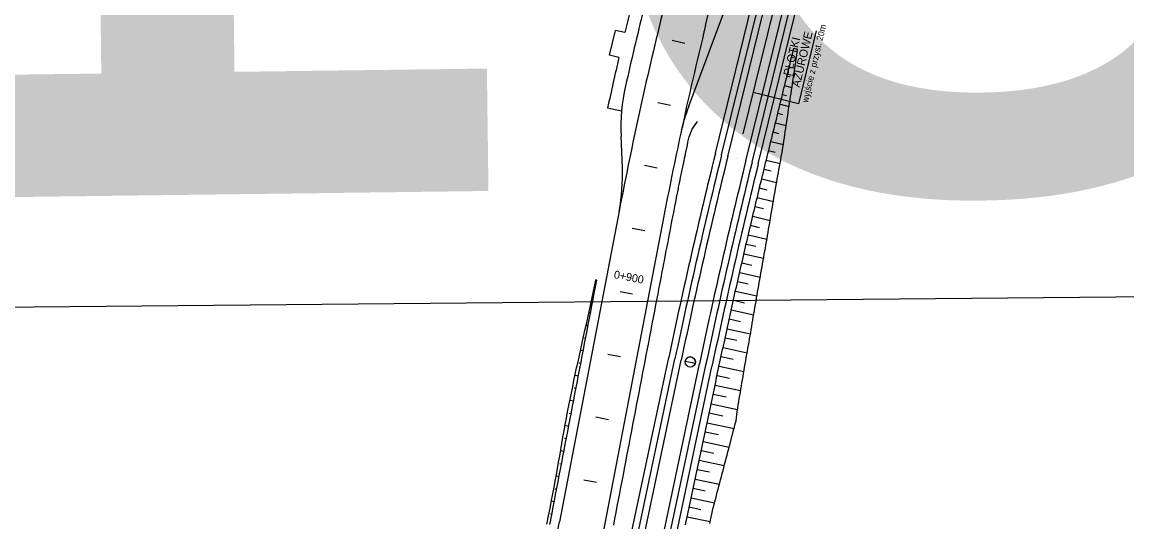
# Model space of a CAD drawing. Extents: x 6503541 to 6503743, y 5888004 to 5888145.
# Drawn here: x 6503704.203 to 6503708.343, y 5888135.392 to 5888137.264 of the extents above; entities that cross this region are included whole.
import ezdxf

# ---------------------------------------------------------------- set-up
doc = ezdxf.new("R2010")
doc.units = 0
doc.layers.add('12', color=7, linetype='Continuous')
doc.layers.add('tabela', color=7, linetype='Continuous')

msp = doc.modelspace()

# ---------------------------------------------------------------- linework, layer by layer
at = {"layer": '12'}
for p, q in [((6503706.9152, 5888136.7445), (6503708.3171, 5888142.443)), ((6503706.9385, 5888136.7388), (6503708.3404, 5888142.4373)), ((6503706.8243, 5888136.7668), (6503708.1987, 5888142.3535)), ((6503706.8476, 5888136.7611), (6503708.222, 5888142.3478)), ((6503706.7644, 5888137.252), (6503706.958, 5888138.0389)), ((6503706.701, 5888136.949), (6503706.8686, 5888137.395)), ((6503706.801, 5888136.7726), (6503706.9378, 5888137.3288)), ((6503707.0189, 5888137.3118), (6503706.9042, 5888136.8457)), ((6503706.9618, 5888136.733), (6503707.0992, 5888137.2916)), ((6503706.4045, 5888137.1396), (6503706.4265, 5888137.2331)), ((6503706.4615, 5888137.2248), (6503706.4265, 5888137.2331)), ((6503707.1781, 5888137.2309), (6503707.113, 5888136.9578)), ((6503707.095, 5888137.1661), (6503707.1093, 5888137.1626)), ((6503706.4395, 5888137.1314), (6503706.4045, 5888137.1396)), ((6503707.0952, 5888137.129), (6503707.0864, 5888137.1311)), ((6503707.0778, 5888137.0962), (6503707.0985, 5888137.0911)), ((6503707.0812, 5888137.0583), (6503707.0692, 5888137.0612)), ((6503707.113, 5888136.9578), (6503706.9421, 5888136.9998)), ((6503707.0606, 5888137.0263), (6503707.0878, 5888137.0196)), ((6503707.0672, 5888136.9876), (6503707.052, 5888136.9913)), ((6503706.3971, 5888136.9429), (6503706.4498, 5888136.9314)), ((6503707.0533, 5888136.9168), (6503707.0348, 5888136.9214)), ((6503707.0434, 5888136.9563), (6503707.0771, 5888136.9481)), ((6503707.0262, 5888136.8864), (6503707.0664, 5888136.8765)), ((6503706.4524, 5888136.72), (6503706.4475, 5888136.8369)), ((6503707.0393, 5888136.8461), (6503707.0176, 5888136.8515)), ((6503707.009, 5888136.8165), (6503707.0557, 5888136.805)), ((6503707.0253, 5888136.7754), (6503707.0004, 5888136.7816)), ((6503707.0101, 5888136.7051), (6503706.9832, 5888136.7116)), ((6503706.9918, 5888136.7466), (6503707.0433, 5888136.7339)), ((6503706.9747, 5888136.6767), (6503707.0306, 5888136.663)), ((6503706.9953, 5888136.6346), (6503706.9662, 5888136.6417)), ((6503706.9577, 5888136.6067), (6503707.0182, 5888136.5921)), ((6503706.4416, 5888136.5624), (6503706.2169, 5888135.3917)), ((6503706.9807, 5888136.5642), (6503706.9493, 5888136.5717)), ((6503706.6066, 5888136.5307), (6503706.3819, 5888135.36)), ((6503706.941, 5888136.5367), (6503707.0061, 5888136.5212)), ((6503706.9245, 5888136.4666), (6503706.9941, 5888136.4503)), ((6503706.9664, 5888136.4937), (6503706.9327, 5888136.5016)), ((6503706.9522, 5888136.4232), (6503706.9163, 5888136.4315)), ((6503706.9082, 5888136.3965), (6503706.9818, 5888136.3795)), ((6503706.9378, 5888136.3527), (6503706.9001, 5888136.3614)), ((6503706.8921, 5888136.3263), (6503706.9691, 5888136.3087)), ((6503706.8762, 5888136.2561), (6503706.9567, 5888136.238)), ((6503706.9235, 5888136.2823), (6503706.8841, 5888136.2912)), ((6503706.9095, 5888136.2117), (6503706.8683, 5888136.2209)), ((6503706.8605, 5888136.1858), (6503706.9445, 5888136.1672)), ((6503706.8956, 5888136.1412), (6503706.8527, 5888136.1506)), ((6503706.845, 5888136.1155), (6503706.9325, 5888136.0964)), ((6503706.8818, 5888136.0707), (6503706.8374, 5888136.0803)), ((6503705.4026, 5888130.2295), (6503706.626, 5888136.008)), ((6503706.8681, 5888136.0001), (6503706.8222, 5888136.0099)), ((6503706.8298, 5888136.0451), (6503706.92, 5888136.0257)), ((6503705.426, 5888130.2245), (6503706.6495, 5888136.003)), ((6503705.4495, 5888130.2195), (6503706.673, 5888135.998)), ((6503705.5176, 5888130.2051), (6503706.7411, 5888135.9836)), ((6503705.5411, 5888130.2001), (6503706.7646, 5888135.9786)), ((6503705.5646, 5888130.1952), (6503706.788, 5888135.9737)), ((6503706.8147, 5888135.9747), (6503706.9078, 5888135.9549)), ((6503706.8545, 5888135.9295), (6503706.8073, 5888135.9395)), ((6503706.7998, 5888135.9042), (6503706.8956, 5888135.884)), ((6503706.841, 5888135.8587), (6503706.7924, 5888135.869)), ((6503706.8285, 5888135.7878), (6503706.7775, 5888135.7986)), ((6503706.7849, 5888135.8338), (6503706.884, 5888135.8128)), ((6503706.77, 5888135.7634), (6503706.8711, 5888135.742)), ((6503706.8122, 5888135.7176), (6503706.7625, 5888135.7281)), ((6503706.7551, 5888135.6929), (6503706.8527, 5888135.6723)), ((6503706.7956, 5888135.6476), (6503706.7476, 5888135.6577)), ((6503706.7402, 5888135.6225), (6503706.8344, 5888135.6025)), ((6503706.7253, 5888135.5521), (6503706.8161, 5888135.5328)), ((6503706.779, 5888135.5775), (6503706.7327, 5888135.5873)), ((6503706.7624, 5888135.5074), (6503706.7178, 5888135.5168)), ((6503706.7103, 5888135.4816), (6503706.7978, 5888135.4631)), ((6503706.746, 5888135.4373), (6503706.7029, 5888135.4464)), ((6503706.6954, 5888135.4112), (6503706.7818, 5888135.3929))]:
    msp.add_line(p, q, dxfattribs=at)
for points in [[(6503706.6863, 5888137.1845), (6503706.6396, 5888137.1957)], [(6503706.689, 5888135.3809), (6503706.6915, 5888135.3926), (6503706.694, 5888135.4044), (6503706.6965, 5888135.4161), (6503706.699, 5888135.4278), (6503706.7014, 5888135.4396), (6503706.7039, 5888135.4513), (6503706.7064, 5888135.4631), (6503706.7089, 5888135.4748), (6503706.7114, 5888135.4865), (6503706.7139, 5888135.4983), (6503706.7164, 5888135.51), (6503706.7188, 5888135.5218), (6503706.7213, 5888135.5335), (6503706.7238, 5888135.5452), (6503706.7263, 5888135.557), (6503706.7288, 5888135.5687), (6503706.7313, 5888135.5804), (6503706.7338, 5888135.5922), (6503706.7362, 5888135.6039), (6503706.7387, 5888135.6157), (6503706.7412, 5888135.6274), (6503706.7437, 5888135.6391), (6503706.7462, 5888135.6509), (6503706.7487, 5888135.6626), (6503706.7512, 5888135.6744), (6503706.7536, 5888135.6861), (6503706.7561, 5888135.6978), (6503706.7586, 5888135.7096), (6503706.7611, 5888135.7213), (6503706.7636, 5888135.7331), (6503706.7661, 5888135.7448), (6503706.7686, 5888135.7565), (6503706.771, 5888135.7683), (6503706.7735, 5888135.78), (6503706.776, 5888135.7918), (6503706.7785, 5888135.8035), (6503706.781, 5888135.8152), (6503706.7835, 5888135.827), (6503706.786, 5888135.8387), (6503706.7884, 5888135.8505), (6503706.7909, 5888135.8622), (6503706.7934, 5888135.8739), (6503706.7959, 5888135.8857), (6503706.7984, 5888135.8974), (6503706.8009, 5888135.9092), (6503706.8034, 5888135.9209), (6503706.8058, 5888135.9326), (6503706.8083, 5888135.9444), (6503706.8108, 5888135.9561), (6503706.8133, 5888135.9679), (6503706.8158, 5888135.9795), (6503706.8183, 5888135.9912), (6503706.8207, 5888136.0029), (6503706.8232, 5888136.0146), (6503706.8257, 5888136.0263), (6503706.8282, 5888136.038), (6503706.8308, 5888136.0496), (6503706.8333, 5888136.0613), (6503706.8358, 5888136.073), (6503706.8383, 5888136.0847), (6503706.8409, 5888136.0963), (6503706.8434, 5888136.108), (6503706.846, 5888136.1197), (6503706.8485, 5888136.1314), (6503706.8511, 5888136.143), (6503706.8536, 5888136.1547), (6503706.8562, 5888136.1664), (6503706.8588, 5888136.178), (6503706.8614, 5888136.1897), (6503706.8639, 5888136.2013), (6503706.8665, 5888136.213), (6503706.8691, 5888136.2247), (6503706.8717, 5888136.2363), (6503706.8744, 5888136.248), (6503706.877, 5888136.2596), (6503706.8796, 5888136.2713), (6503706.8822, 5888136.2829), (6503706.8849, 5888136.2946), (6503706.8875, 5888136.3062), (6503706.8901, 5888136.3179), (6503706.8928, 5888136.3295), (6503706.8955, 5888136.3412), (6503706.8981, 5888136.3528), (6503706.9008, 5888136.3645), (6503706.9035, 5888136.3761), (6503706.9061, 5888136.3878), (6503706.9088, 5888136.3994), (6503706.9115, 5888136.411), (6503706.9142, 5888136.4227), (6503706.9169, 5888136.4343), (6503706.9196, 5888136.4459), (6503706.9224, 5888136.4576), (6503706.9251, 5888136.4692), (6503706.9278, 5888136.4808), (6503706.9305, 5888136.4925), (6503706.9333, 5888136.5041), (6503706.936, 5888136.5157), (6503706.9388, 5888136.5273), (6503706.9415, 5888136.539), (6503706.9443, 5888136.5506), (6503706.9471, 5888136.5622), (6503706.9498, 5888136.5738), (6503706.9526, 5888136.5854), (6503706.9554, 5888136.5971), (6503706.9582, 5888136.6087), (6503706.961, 5888136.6203), (6503706.9638, 5888136.6319), (6503706.9666, 5888136.6435), (6503706.9694, 5888136.6551), (6503706.9722, 5888136.6667), (6503706.9751, 5888136.6783), (6503706.9779, 5888136.6899), (6503706.9807, 5888136.7015), (6503706.9836, 5888136.7131), (6503706.9864, 5888136.7247), (6503706.9893, 5888136.7364), (6503706.9922, 5888136.748), (6503706.995, 5888136.7597), (6503706.9979, 5888136.7713), (6503707.0008, 5888136.783), (6503707.0036, 5888136.7947), (6503707.0065, 5888136.8063), (6503707.0094, 5888136.818), (6503707.0122, 5888136.8296), (6503707.0151, 5888136.8413), (6503707.018, 5888136.8529), (6503707.0208, 5888136.8646), (6503707.0237, 5888136.8762), (6503707.0266, 5888136.8879), (6503707.0294, 5888136.8995), (6503707.0323, 5888136.9112), (6503707.0352, 5888136.9228), (6503707.038, 5888136.9345), (6503707.0409, 5888136.9461), (6503707.0438, 5888136.9578), (6503707.0466, 5888136.9694), (6503707.0495, 5888136.9811), (6503707.0524, 5888136.9927), (6503707.0552, 5888137.0044), (6503707.0581, 5888137.0161), (6503707.061, 5888137.0277), (6503707.0638, 5888137.0394), (6503707.0667, 5888137.051), (6503707.0696, 5888137.0627), (6503707.0724, 5888137.0743), (6503707.0753, 5888137.086), (6503707.0782, 5888137.0976), (6503707.081, 5888137.1093), (6503707.0839, 5888137.1209), (6503707.0868, 5888137.1326), (6503707.0896, 5888137.1442), (6503707.0925, 5888137.1559), (6503707.095, 5888137.1661)], [(6503706.7804, 5888135.3861), (6503706.7828, 5888135.3978), (6503706.7852, 5888135.4096), (6503706.7877, 5888135.4213), (6503706.7901, 5888135.4331), (6503706.793, 5888135.4447), (6503706.796, 5888135.4563), (6503706.7991, 5888135.468), (6503706.8021, 5888135.4796), (6503706.8052, 5888135.4912), (6503706.8082, 5888135.5028), (6503706.8113, 5888135.5144), (6503706.8143, 5888135.5261), (6503706.8174, 5888135.5377), (6503706.8204, 5888135.5493), (6503706.8235, 5888135.5609), (6503706.8265, 5888135.5725), (6503706.8296, 5888135.5842), (6503706.8326, 5888135.5958), (6503706.8357, 5888135.6074), (6503706.8388, 5888135.619), (6503706.8418, 5888135.6306), (6503706.8449, 5888135.6423), (6503706.8479, 5888135.6539), (6503706.851, 5888135.6655), (6503706.854, 5888135.6771), (6503706.8571, 5888135.6887), (6503706.8601, 5888135.7004), (6503706.8632, 5888135.712), (6503706.8662, 5888135.7236), (6503706.8693, 5888135.7352), (6503706.8723, 5888135.7468), (6503706.8754, 5888135.7585), (6503706.8784, 5888135.7701), (6503706.8804, 5888135.7819), (6503706.8818, 5888135.7939), (6503706.8832, 5888135.8059), (6503706.8846, 5888135.8178), (6503706.8864, 5888135.8297), (6503706.8884, 5888135.8416), (6503706.8904, 5888135.8534), (6503706.8924, 5888135.8652), (6503706.8945, 5888135.8771), (6503706.8965, 5888135.8889), (6503706.8985, 5888135.9008), (6503706.9005, 5888135.9126), (6503706.9026, 5888135.9244), (6503706.9046, 5888135.9363), (6503706.9066, 5888135.9481), (6503706.9086, 5888135.9598), (6503706.9106, 5888135.9716), (6503706.9127, 5888135.9833), (6503706.9147, 5888135.995), (6503706.9167, 5888136.0068), (6503706.9188, 5888136.0185), (6503706.9208, 5888136.0302), (6503706.9229, 5888136.042), (6503706.9249, 5888136.0537), (6503706.927, 5888136.0654), (6503706.9291, 5888136.0772), (6503706.9312, 5888136.0889), (6503706.9333, 5888136.1006), (6503706.9353, 5888136.1123), (6503706.9373, 5888136.1241), (6503706.9392, 5888136.1358), (6503706.9412, 5888136.1476), (6503706.9432, 5888136.1593), (6503706.9452, 5888136.1711), (6503706.9472, 5888136.1828), (6503706.9492, 5888136.1946), (6503706.9513, 5888136.2063), (6503706.9533, 5888136.2181), (6503706.9553, 5888136.2298), (6503706.9574, 5888136.2416), (6503706.9594, 5888136.2533), (6503706.9615, 5888136.265), (6503706.9635, 5888136.2768), (6503706.9656, 5888136.2885), (6503706.9676, 5888136.3003), (6503706.9697, 5888136.312), (6503706.9718, 5888136.3237), (6503706.9739, 5888136.3355), (6503706.976, 5888136.3472), (6503706.9781, 5888136.3589), (6503706.9802, 5888136.3707), (6503706.9823, 5888136.3824), (6503706.9844, 5888136.3941), (6503706.9866, 5888136.4059), (6503706.9887, 5888136.4176), (6503706.9906, 5888136.4294), (6503706.9926, 5888136.4412), (6503706.9946, 5888136.4529), (6503706.9965, 5888136.4647), (6503706.9985, 5888136.4765), (6503707.0005, 5888136.4882), (6503707.0025, 5888136.5), (6503707.0045, 5888136.5118), (6503707.0065, 5888136.5235), (6503707.0085, 5888136.5353), (6503707.0105, 5888136.5471), (6503707.0125, 5888136.5589), (6503707.0145, 5888136.5706), (6503707.0165, 5888136.5824), (6503707.0186, 5888136.5941), (6503707.0206, 5888136.6059), (6503707.0227, 5888136.6177), (6503707.0247, 5888136.6294), (6503707.0268, 5888136.6412), (6503707.0289, 5888136.653), (6503707.0309, 5888136.6647), (6503707.033, 5888136.6765), (6503707.0351, 5888136.6882), (6503707.0372, 5888136.7), (6503707.0393, 5888136.7117), (6503707.0414, 5888136.7236), (6503707.0435, 5888136.7354), (6503707.0458, 5888136.7472), (6503707.0481, 5888136.759), (6503707.0504, 5888136.7708), (6503707.0523, 5888136.7827), (6503707.0541, 5888136.7946), (6503707.0559, 5888136.8065), (6503707.0577, 5888136.8184), (6503707.0595, 5888136.8303), (6503707.0613, 5888136.8423), (6503707.063, 5888136.8542), (6503707.0648, 5888136.8661), (6503707.0666, 5888136.878), (6503707.0684, 5888136.8899), (6503707.0702, 5888136.9019), (6503707.072, 5888136.9138), (6503707.0738, 5888136.9257), (6503707.0755, 5888136.9376), (6503707.0773, 5888136.9495), (6503707.0791, 5888136.9614), (6503707.0809, 5888136.9734), (6503707.0827, 5888136.9853), (6503707.0845, 5888136.9972), (6503707.0863, 5888137.0091), (6503707.0881, 5888137.021), (6503707.0898, 5888137.033), (6503707.0916, 5888137.0449), (6503707.0934, 5888137.0568), (6503707.0952, 5888137.0687), (6503707.097, 5888137.0806), (6503707.0988, 5888137.0925), (6503707.1006, 5888137.1045), (6503707.1023, 5888137.1164), (6503707.1041, 5888137.1283), (6503707.1059, 5888137.1402), (6503707.1093, 5888137.1626)], [(6503706.6324, 5888136.9511), (6503706.5855, 5888136.9615)], [(6503706.4199, 5888135.3797), (6503706.4244, 5888135.4033), (6503706.4289, 5888135.4269), (6503706.4335, 5888135.4504), (6503706.438, 5888135.474), (6503706.4425, 5888135.4976), (6503706.447, 5888135.5212), (6503706.4516, 5888135.5447), (6503706.4561, 5888135.5683), (6503706.4606, 5888135.5919), (6503706.4651, 5888135.6154), (6503706.4697, 5888135.639), (6503706.4742, 5888135.6626), (6503706.4787, 5888135.6861), (6503706.4832, 5888135.7097), (6503706.4878, 5888135.7333), (6503706.4923, 5888135.7569), (6503706.4968, 5888135.7804), (6503706.5013, 5888135.804), (6503706.5059, 5888135.8276), (6503706.5104, 5888135.8511), (6503706.5149, 5888135.8747), (6503706.5194, 5888135.8983), (6503706.524, 5888135.9218), (6503706.5285, 5888135.9454), (6503706.533, 5888135.969), (6503706.5375, 5888135.9926), (6503706.542, 5888136.0161), (6503706.5466, 5888136.0397), (6503706.5511, 5888136.0633), (6503706.5556, 5888136.0868), (6503706.5601, 5888136.1104), (6503706.5647, 5888136.134), (6503706.5692, 5888136.1575), (6503706.5737, 5888136.1811), (6503706.5782, 5888136.2047), (6503706.5828, 5888136.2282), (6503706.5873, 5888136.2518), (6503706.5897, 5888136.2644), (6503706.5918, 5888136.2754), (6503706.5963, 5888136.299), (6503706.5989, 5888136.3122), (6503706.6009, 5888136.3225), (6503706.6054, 5888136.3461), (6503706.608, 5888136.3599), (6503706.6099, 5888136.3697), (6503706.6144, 5888136.3932), (6503706.6172, 5888136.4077), (6503706.619, 5888136.4168), (6503706.6235, 5888136.4404), (6503706.6264, 5888136.4555), (6503706.628, 5888136.4639), (6503706.6325, 5888136.4875), (6503706.6355, 5888136.5032), (6503706.6371, 5888136.5111), (6503706.6396, 5888136.5244), (6503706.6416, 5888136.5346), (6503706.6428, 5888136.5408), (6503706.6447, 5888136.5508), (6503706.646, 5888136.5572), (6503706.6461, 5888136.5579), (6503706.6492, 5888136.5737), (6503706.6507, 5888136.5813), (6503706.6524, 5888136.5901), (6503706.654, 5888136.5982), (6503706.6553, 5888136.6047), (6503706.6556, 5888136.6065), (6503706.6589, 5888136.6229), (6503706.6599, 5888136.628), (6503706.6622, 5888136.6394), (6503706.6634, 5888136.6455), (6503706.6646, 5888136.6513), (6503706.6655, 5888136.6558), (6503706.6688, 5888136.6722), (6503706.6693, 5888136.6747), (6503706.6721, 5888136.6886), (6503706.673, 5888136.6928), (6503706.674, 5888136.698), (6503706.6755, 5888136.705), (6503706.6788, 5888136.7213), (6503706.6789, 5888136.7214), (6503706.6823, 5888136.7378), (6503706.6827, 5888136.74), (6503706.6837, 5888136.7446), (6503706.6857, 5888136.7542), (6503706.6886, 5888136.7679), (6503706.6891, 5888136.7706), (6503706.6926, 5888136.787), (6503706.6926, 5888136.7872), (6503706.6935, 5888136.7912), (6503706.696, 5888136.8033), (6503706.6984, 5888136.8145), (6503706.6995, 5888136.8197), (6503706.7027, 5888136.8344), (6503706.7141, 5888136.8636), (6503706.7336, 5888136.8915)], [(6503706.5824, 5888136.7168), (6503706.5353, 5888136.7264)], [(6503706.5361, 5888136.4816), (6503706.4889, 5888136.4906)], [(6503706.1699, 5888135.3835), (6503706.1731, 5888135.4001), (6503706.1736, 5888135.4026), (6503706.1782, 5888135.4261), (6503706.1827, 5888135.4497), (6503706.1873, 5888135.4733), (6503706.1918, 5888135.4968), (6503706.1964, 5888135.5204), (6503706.2009, 5888135.544), (6503706.2051, 5888135.5676), (6503706.2093, 5888135.5912), (6503706.2134, 5888135.6149), (6503706.2176, 5888135.6385), (6503706.2217, 5888135.6622), (6503706.2258, 5888135.6858), (6503706.23, 5888135.7094), (6503706.2341, 5888135.7331), (6503706.2383, 5888135.7567), (6503706.2426, 5888135.7803), (6503706.2474, 5888135.8039), (6503706.2521, 5888135.8274), (6503706.2569, 5888135.8509), (6503706.2617, 5888135.8744), (6503706.2664, 5888135.898), (6503706.2712, 5888135.9215), (6503706.276, 5888135.945), (6503706.2811, 5888135.9685), (6503706.2863, 5888135.9919), (6503706.2915, 5888136.0153), (6503706.2967, 5888136.0388), (6503706.3019, 5888136.0622), (6503706.3071, 5888136.0857), (6503706.3123, 5888136.1091), (6503706.3175, 5888136.1325), (6503706.3227, 5888136.156), (6503706.3279, 5888136.1794), (6503706.3331, 5888136.2029), (6503706.3383, 5888136.2263), (6503706.3435, 5888136.2497), (6503706.3482, 5888136.2733), (6503706.3529, 5888136.2968), (6503706.3531, 5888136.298)], [(6503706.1807, 5888135.3814), (6503706.1839, 5888135.398), (6503706.1844, 5888135.4005), (6503706.1889, 5888135.4241), (6503706.1934, 5888135.4476), (6503706.198, 5888135.4712), (6503706.2025, 5888135.4948), (6503706.207, 5888135.5184), (6503706.2115, 5888135.5419), (6503706.2161, 5888135.5655), (6503706.2206, 5888135.5891), (6503706.2251, 5888135.6126), (6503706.2296, 5888135.6362), (6503706.2342, 5888135.6598), (6503706.2387, 5888135.6833), (6503706.2432, 5888135.7069), (6503706.2477, 5888135.7305), (6503706.2523, 5888135.754), (6503706.2568, 5888135.7776), (6503706.2613, 5888135.8012), (6503706.2658, 5888135.8248), (6503706.2703, 5888135.8483), (6503706.2749, 5888135.8719), (6503706.2794, 5888135.8955), (6503706.2839, 5888135.919), (6503706.2884, 5888135.9426), (6503706.293, 5888135.9662), (6503706.2975, 5888135.9897), (6503706.302, 5888136.0133), (6503706.3065, 5888136.0369), (6503706.3111, 5888136.0605), (6503706.3156, 5888136.084), (6503706.3201, 5888136.1076), (6503706.3246, 5888136.1312), (6503706.3292, 5888136.1547), (6503706.3337, 5888136.1783), (6503706.3382, 5888136.2019), (6503706.3427, 5888136.2254), (6503706.3473, 5888136.249), (6503706.3518, 5888136.2726), (6503706.3565, 5888136.2974)], [(6503706.3565, 5888136.2974), (6503706.3531, 5888136.298)], [(6503706.3509, 5888136.2681), (6503706.3491, 5888136.2685)], [(6503706.4437, 5888136.2549), (6503706.4908, 5888136.2459)], [(6503706.3419, 5888136.221), (6503706.3373, 5888136.2219)], [(6503706.3328, 5888136.1738), (6503706.3299, 5888136.1744)], [(6503706.3238, 5888136.1267), (6503706.3165, 5888136.1281)], [(6503706.3147, 5888136.0796), (6503706.3104, 5888136.0804)], [(6503706.3057, 5888136.0324), (6503706.2957, 5888136.0343)], [(6503706.4456, 5888136.0102), (6503706.3985, 5888136.0192)], [(6503706.2966, 5888135.9853), (6503706.291, 5888135.9864)], [(6503706.6883, 5888135.9943), (6503706.7259, 5888135.9865)], [(6503706.2876, 5888135.9381), (6503706.2751, 5888135.9405)], [(6503706.2785, 5888135.891), (6503706.272, 5888135.8922)], [(6503706.2695, 5888135.8439), (6503706.256, 5888135.8465)], [(6503706.2604, 5888135.7967), (6503706.2535, 5888135.7981)], [(6503706.4004, 5888135.7745), (6503706.3532, 5888135.7835)], [(6503706.2514, 5888135.7496), (6503706.2375, 5888135.7523)], [(6503706.2423, 5888135.7024), (6503706.2358, 5888135.7037)], [(6503706.2333, 5888135.6553), (6503706.2209, 5888135.6577)], [(6503706.2242, 5888135.6082), (6503706.2184, 5888135.6093)], [(6503706.2152, 5888135.561), (6503706.2043, 5888135.5631)], [(6503706.2061, 5888135.5139), (6503706.2008, 5888135.5149)], [(6503706.3551, 5888135.5388), (6503706.308, 5888135.5478)], [(6503706.1971, 5888135.4667), (6503706.1864, 5888135.4688)], [(6503706.188, 5888135.4196), (6503706.1827, 5888135.4206)]]:
    msp.add_lwpolyline(points, dxfattribs=at)
msp.add_circle((6503706.707, 5888135.9908), 0.0192, dxfattribs=at)
for centre, radius, start, end in [((6503720.666, 5888133.8321), 14.604, 165.58417, 166.5665), ((6503720.666, 5888133.8321), 14.484, 166.1792, 169.13463), ((6503720.666, 5888133.8321), 14.556, 166.1792, 167.32982), ((6503720.666, 5888133.8321), 14.316, 166.1792, 167.84106), ((6503720.666, 5888133.8321), 14.604, 166.94314, 167.70119), ((6503707.1669, 5888136.8669), 0.72, 167.3298, 182.3826), ((6503707.375, 5888136.6957), 0.72, 159.4022, 167.8411), ((6503720.666, 5888133.8321), 14.316, 167.84106, 169.13463), ((6503730.1865, 5888131.0195), 24.0828, 166.1792, 168.04536), ((6503730.1865, 5888131.0195), 24.0588, 166.1792, 168.04536), ((6503730.1865, 5888131.0195), 24.0348, 166.1792, 168.04536), ((6503705.733, 5888136.6901), 0.72, 349.1653, 2.3826), ((6503730.1865, 5888131.0195), 23.9652, 166.1792, 168.04536), ((6503730.1865, 5888131.0195), 23.9412, 166.1792, 168.04536), ((6503730.1865, 5888131.0195), 23.9172, 166.1792, 168.04536), ((6503706.7071, 5888135.9904), 0.0192, 43.9367, 168.3839), ((6503706.7071, 5888135.9904), 0.0192, 348.3839, 43.9367), ((6503692.1576, 5888138.0903), 14.316, 348.04536, 349.13463)]:
    msp.add_arc(centre, radius, start, end, dxfattribs=at)
at = {"layer": 'tabela'}
msp.add_line((6503710.6131, 5888136.2556), (6503703.3777, 5888136.188), dxfattribs=at)
msp.add_line((6503710.6131, 5888136.2556), (6503703.3777, 5888136.188), dxfattribs=at)

# ---------------------------------------------------------------- texts
at = {"layer": '12'}
for s, height, rotation, p in [('18', 4.22297, 0.7393, (6503703.0861, 5888136.5945)), ('wyjście z przyst. 20m', 0.023802, 76.6742, (6503707.1473, 5888136.96)), ('PŁOTKI', 0.0311, 76.6742, (6503707.0852, 5888137.0597)), ('AŻUROWE', 0.0311, 76.6742, (6503707.1166, 5888137.0175)), ('C', 0.0024, 76.1792, (6503706.8823, 5888136.7513)), ('0+900', 0.03, 349.1346, (6503706.4188, 5888136.3049)), ('C', 0.0024, 78.0454, (6503706.708, 5888135.9894))]:
    msp.add_text(s, height=height, rotation=rotation, dxfattribs=at).set_placement(p)

doc.saveas('drawing.dxf')
